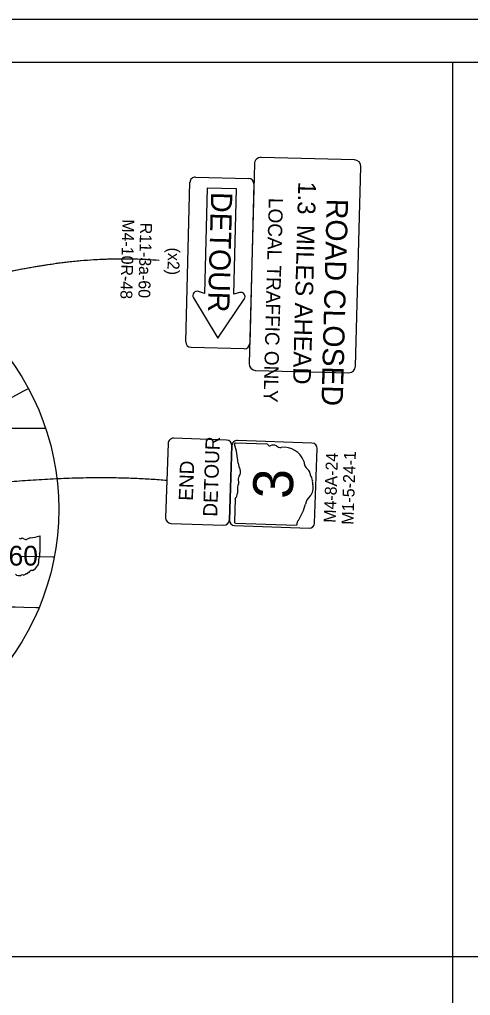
# Model space of a CAD drawing. Extents: x -15.3 to 34, y 0 to 22.
# Drawn here: x 11.66 to 16.96, y 10.54 to 22 of the extents above; entities that cross this region are included whole.
import ezdxf

# ---------------------------------------------------------------- set-up
doc = ezdxf.new("R2010")
doc.units = 0
for name, color, linetype in [('GM_X_City_Street', 7, 'Continuous'), ('GM_X_State_Route', 7, 'Continuous'), ('GM_X_State_Shield', 7, 'Continuous'), ('GM_X_Township', 7, 'Continuous'), ('SC_Scratch1', 7, 'Continuous'), ('SH_Border', 7, 'Continuous'), ('SH_Cut_Line', 7, 'Continuous'), ('SH_Text', 7, 'Continuous'), ('SN_P_Signs', 7, 'Continuous')]:
    doc.layers.add(name, color=color, linetype=linetype)

msp = doc.modelspace()

# ---------------------------------------------------------------- linework, layer by layer
at = {"layer": 'GM_X_City_Street'}
msp.add_lwpolyline([(11.302, 15.108), (11.343, 15.108), (11.432, 15.106), (11.526, 15.104), (11.611, 15.103), (11.716, 15.101), (11.86, 15.098), (11.895, 15.097)], dxfattribs=at)
at = {"layer": 'GM_X_State_Route'}
for points in [[(11.409, 17.477), (11.705, 17.635), (11.768, 17.669)], [(11.662, 15.698), (11.902, 15.695), (12.055, 15.693), (12.073, 15.692)]]:
    msp.add_lwpolyline(points, dxfattribs=at)
at = {"layer": 'GM_X_State_Shield'}
for q in [(11.907, 15.931), (11.907, 15.747)]:
    msp.add_line((11.907, 15.747), q, dxfattribs=at)
for centre, radius, start, end in [((11.741, 16.403), 0.492, 275.8445, 288.9065), ((11.902, 15.932), 0.00517, 351.8621, 97.738), ((11.675, 15.919), 0.015, 219.7921, 297.1024), ((11.697, 15.878), 0.0313, 54.4667, 119.1411), ((11.738, 15.934), 0.0376, 233.8562, 294.8282), ((11.804, 15.815), 0.099, 97.3462, 120.7689), ((11.905, 15.734), 0.00799, 107.944, 210.337), ((11.855, 15.71), 0.048, 340.033, 23.6496), ((11.901, 15.746), 0.00553, 289.6038, 7.7341), ((11.769, 15.647), 0.123, 292.3089, 8.9858), ((11.925, 15.67), 0.0349, 136.8065, 186.9296), ((11.66, 15.542), 0.0706, 230.7004, 286.2918), ((11.701, 15.421), 0.058, 85.6951, 111.2099), ((11.706, 15.516), 0.0376, 268.777, 315.5493), ((11.74, 15.482), 0.0106, 65.7517, 132.6484), ((11.735, 15.53), 0.0398, 282.8732, 323.2771), ((11.821, 15.465), 0.0674, 94.4031, 142.5768)]:
    msp.add_arc(centre, radius, start, end, dxfattribs=at)
at = {"layer": 'GM_X_Township'}
msp.add_line((6.276, 17.19), (11.969, 17.203), dxfattribs=at)
at = {"layer": 'SH_Border'}
msp.add_lwpolyline([(1.5, 21.5), (33.5, 21.5), (33.5, 0.5), (1.5, 0.5)], close=True, dxfattribs=at)
at = {"layer": 'SH_Cut_Line'}
msp.add_lwpolyline([(0, 0), (34, 0), (34, 22), (0, 22)], close=True, dxfattribs=at)
at = {"layer": 'SH_Text'}
for p, q in [((16.75, 0.5), (16.75, 21.5)), ((1.5, 11), (32, 11))]:
    msp.add_line(p, q, dxfattribs=at)
msp.add_circle((9.125, 16.25), 3, dxfattribs=at)
for points in [[(13.302, 19.171), (12.298, 19.253), (9.979, 18.624), (9.436, 17.313), (9.246, 17.097)], [(13.302, 19.171), (12.298, 19.253), (9.979, 18.624), (9.436, 17.313), (9.246, 16.848)], [(13.393, 16.587), (12.757, 16.643), (11.217, 16.559), (9.878, 16.33), (9.878, 15.933), (9.321, 15.901)]]:
    msp.add_open_spline(points, degree=2, dxfattribs=at)
at = {"layer": 'SN_P_Signs'}
for p, q in [((13.867, 20.022), (13.834, 18.783)), ((14.21, 20.013), (13.867, 20.022)), ((14.178, 18.774), (14.21, 20.013)), ((13.834, 18.783), (13.766, 18.807)), ((14.248, 18.794), (14.178, 18.774)), ((13.706, 18.734), (13.992, 18.258)), ((13.992, 18.258), (14.303, 18.718)), ((14.573, 17.014), (14.201, 17.027)), ((14.573, 17.014), (14.573, 17.014)), ((14.196, 16.373), (14.187, 16.099)), ((14.199, 16.089), (14.91, 16.064))]:
    msp.add_line(p, q, dxfattribs=at)
for points in [[(14.421, 20.304), (14.36, 17.961)], [(15.595, 20.352), (14.501, 20.381)], [(15.609, 17.929), (15.671, 20.272)], [(13.616, 18.215), (13.665, 20.09)], [(13.729, 20.151), (14.354, 20.134)], [(14.415, 20.07), (14.366, 18.196)], [(14.302, 18.135), (13.677, 18.151)], [(14.436, 17.881), (15.529, 17.853)], [(14.095, 17.063), (13.476, 17.084)], [(13.408, 17.021), (13.378, 16.152)], [(14.158, 16.998), (14.128, 16.123)], [(14.128, 16.126), (14.158, 16.995)], [(15.097, 17.028), (14.223, 17.058)], [(15.127, 16.089), (15.157, 16.963)], [(13.441, 16.085), (14.061, 16.063)], [(14.188, 16.059), (15.063, 16.029)]]:
    msp.add_lwpolyline(points, dxfattribs=at)
for centre, radius, start, end in [((14.499, 20.302), 0.0781, 88.5011, 178.5011), ((15.593, 20.274), 0.0781, 358.5011, 88.5011), ((13.728, 20.088), 0.0625, 88.5011, 178.5011), ((14.353, 20.072), 0.0625, 358.5011, 88.5011), ((13.749, 18.76), 0.05, 70.6822, 211.0119), ((14.262, 18.746), 0.05, 325.9902, 106.32), ((13.679, 18.214), 0.0625, 178.5011, 268.5011), ((14.304, 18.197), 0.0625, 268.5011, 358.5011), ((14.438, 17.959), 0.0781, 178.5011, 268.5011), ((15.531, 17.931), 0.0781, 268.5011, 358.5011), ((13.473, 17.019), 0.065, 88.0207, 178.0207), ((14.093, 16.998), 0.065, 358.0207, 88.0207), ((14.22, 16.996), 0.0625, 88.0207, 178.0207), ((14.199, 17.017), 0.0104, 79.8828, 185.7587), ((13.238, 16.726), 0.994, 3.8652, 16.9272), ((14.574, 17.003), 0.0112, 17.6245, 95.7549), ((14.6, 17.011), 0.0162, 195.9647, 298.3577), ((14.644, 16.906), 0.097, 68.0537, 111.6703), ((14.73, 17.046), 0.0705, 224.8272, 274.9503), ((14.767, 16.729), 0.249, 20.3296, 97.0066), ((15.095, 16.965), 0.0625, 358.0207, 88.0207), ((14.429, 16.812), 0.2, 185.3669, 208.7896), ((15.136, 16.821), 0.136, 182.4238, 230.5975), ((14.293, 16.601), 0.0632, 142.4874, 207.1619), ((14.184, 16.686), 0.076, 321.8769, 22.8489), ((14.999, 16.653), 0.0803, 10.8939, 51.2978), ((15.097, 16.659), 0.0214, 153.7725, 220.6691), ((15.026, 16.593), 0.0759, 356.7977, 43.57), ((14.599, 16.459), 0.378, 168.5074, 183.009), ((14.21, 16.559), 0.0304, 307.8128, 25.1231), ((14.969, 16.502), 0.143, 318.7211, 14.3126), ((15.218, 16.576), 0.117, 173.7158, 199.2307), ((14.116, 16.441), 0.105, 319.6402, 359.1326), ((15.236, 16.249), 0.225, 135.2049, 163.8567), ((14.326, 16.495), 0.718, 328.4336, 345.2192), ((13.443, 16.15), 0.065, 178.0207, 268.0207), ((14.063, 16.128), 0.065, 268.0207, 358.0207), ((14.19, 16.121), 0.0625, 178.0207, 268.0207), ((14.198, 16.1), 0.0109, 186.1508, 276.1508), ((14.912, 16.075), 0.011, 259.9791, 346.3273), ((14.952, 16.093), 0.0302, 117.7691, 181.2925), ((14.839, 16.079), 0.0836, 355.3597, 8.6246), ((15.065, 16.091), 0.0625, 268.0207, 358.0207)]:
    msp.add_arc(centre, radius, start, end, dxfattribs=at)

# ---------------------------------------------------------------- texts
at = {"layer": 'GM_X_State_Shield'}
msp.add_text('60', height=0.232, dxfattribs=at).set_placement((11.535, 15.589))
at = {"layer": 'SC_Scratch1'}
for s, rotation, p in [('M4-10R-48', 268.5011, (12.872, 19.656)), ('R11-3a-60', 268.5011, (13.081, 19.616)), ('M4-8A-24', 88.0207, (15.375, 16.09)), ('M1-5-24-1', 88.0207, (15.584, 16.067))]:
    msp.add_text(s, height=0.14, rotation=rotation, dxfattribs=at).set_placement(p)
at = {"layer": 'SH_Text'}
msp.add_text('(x2)', height=0.14, rotation=268.5011, dxfattribs=at).set_placement((13.407, 19.324))
at = {"layer": 'SN_P_Signs'}
for s, height, rotation, p in [('1.3', 0.2083, 268.5011, (14.937, 20.1)), ('DETOUR', 0.25, 268.5011, (13.913, 19.977)), ('LOCAL TRAFFIC ONLY', 0.16667, 268.5011, (14.591, 19.907)), ('ROAD CLOSED', 0.25, 268.5011, (15.272, 19.898)), ('MILES AHEAD', 0.20833, 268.5011, (14.923, 19.59)), ('DETOUR', 0.1667, 88.0207, (13.984, 16.161)), ('END', 0.1667, 88.0207, (13.699, 16.348)), ('3', 0.469, 88.0207, (14.87, 16.368))]:
    msp.add_text(s, height=height, rotation=rotation, dxfattribs=at).set_placement(p)

doc.saveas('drawing.dxf')
